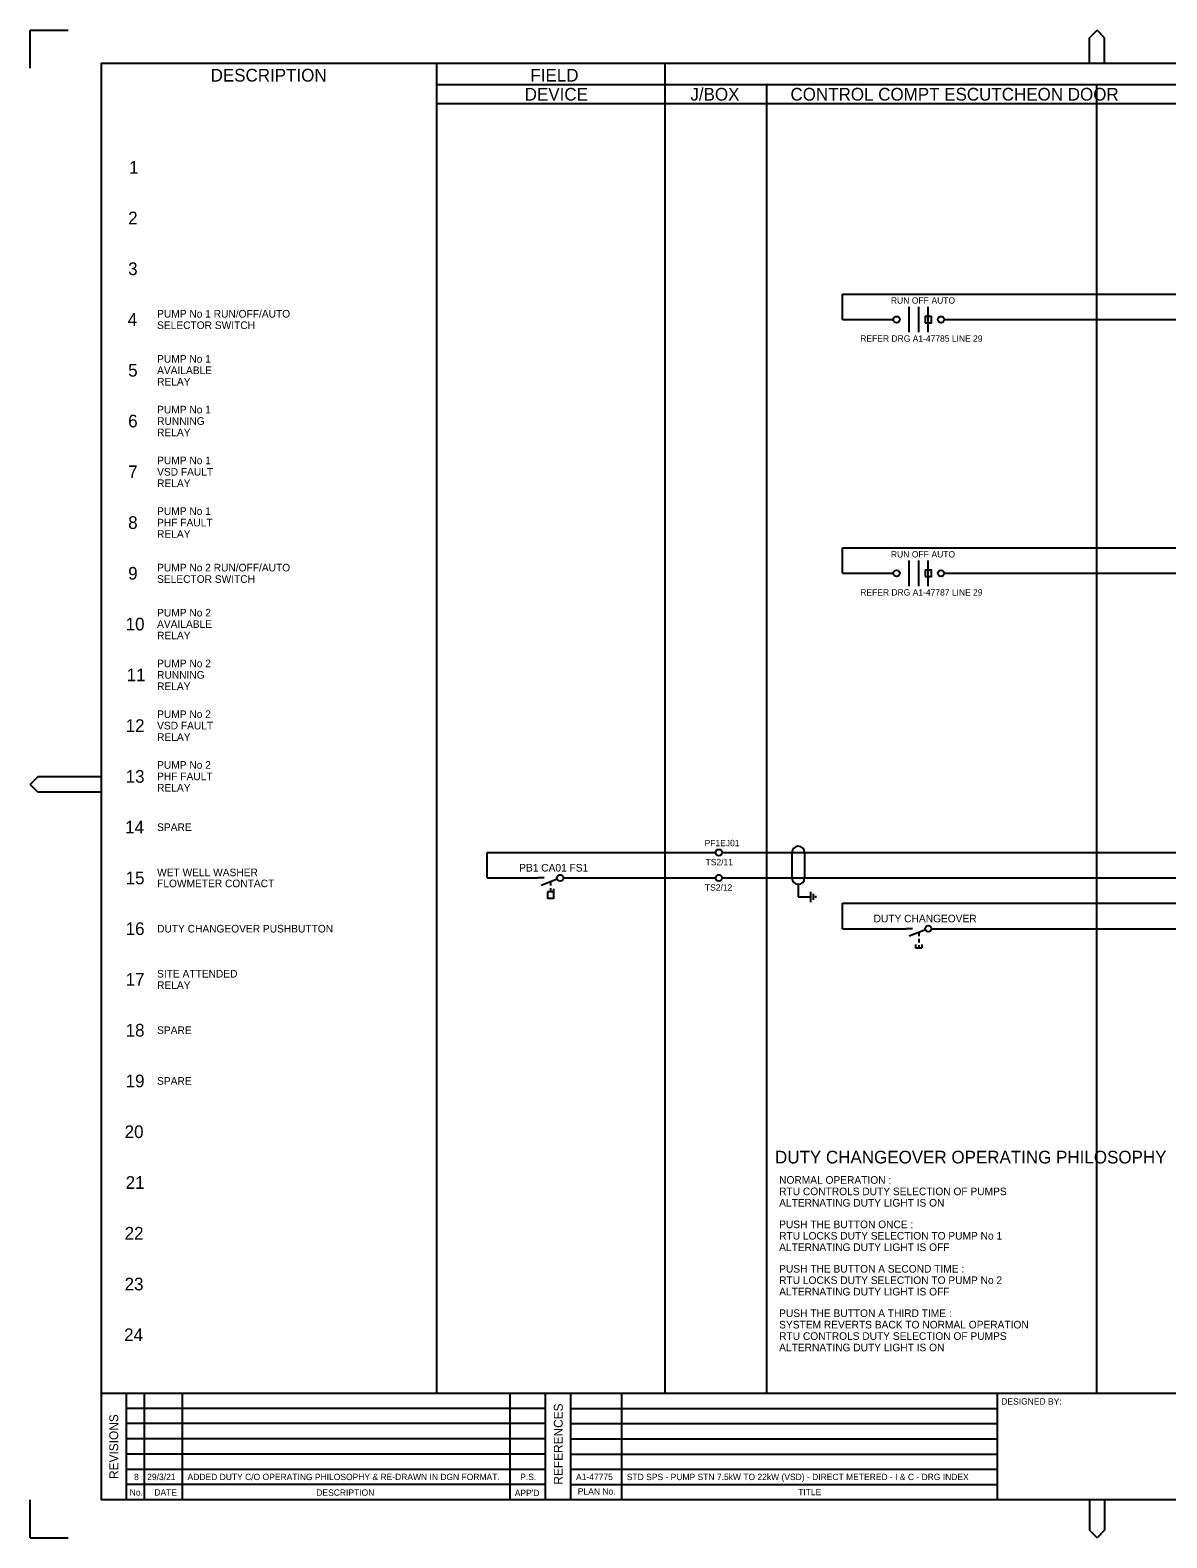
# Model space of a CAD drawing. Extents: x 0 to 841, y 0 to 594.
# Drawn here: x 0 to 448, y 0 to 594 of the extents above; entities that cross this region are included whole.
import ezdxf

# ---------------------------------------------------------------- set-up
doc = ezdxf.new("R2010")
doc.units = 0
for name, color, linetype in [('A1BORDER', 7, 'Continuous'), ('Level 1', 7, 'Continuous'), ('Level 10', 7, 'Continuous'), ('Level 5', 7, 'Continuous')]:
    doc.layers.add(name, color=color, linetype=linetype)

msp = doc.modelspace()

# ---------------------------------------------------------------- linework, layer by layer
at = {"layer": 'A1BORDER'}
for p, q in [((0, 594), (15, 594)), ((0, 579), (0, 594)), ((417.19, 591), (420.19, 594)), ((417.19, 581), (417.19, 591)), ((423.19, 591), (420.19, 594)), ((423.19, 581), (423.19, 591)), ((28, 581), (829, 581)), ((28, 581), (28, 15)), ((3, 299.76), (0, 296.76)), ((28, 299.76), (3, 299.76)), ((3, 293.76), (0, 296.76)), ((28, 293.76), (3, 293.76)), ((28, 57), (829, 57)), ((38, 15), (38, 57)), ((45, 15), (45, 57)), ((60, 15), (60, 57)), ((189, 15), (189, 57)), ((203, 15), (203, 57)), ((213, 15), (213, 57)), ((233, 15), (233, 57)), ((381, 15), (381, 57)), ((203, 51), (38, 51)), ((213, 51), (381, 51)), ((203, 45), (38, 45)), ((213, 45), (381, 45)), ((203, 39), (38, 39)), ((213, 39), (381, 39)), ((203, 33), (38, 33)), ((213, 33), (381, 33)), ((38, 27), (203, 27)), ((213, 27), (381, 27)), ((203, 21), (38, 21)), ((213, 21), (381, 21)), ((0, 0), (0, 15)), ((829, 15), (28, 15)), ((417.19, 15), (417.19, 3)), ((423.19, 15), (423.19, 3)), ((417.19, 3), (420.19, 0)), ((423.19, 3), (420.19, 0)), ((0, 0), (15, 0))]:
    msp.add_line(p, q, dxfattribs=at)
at = {"layer": 'Level 1'}
for p, q in [((160, 581), (160, 57)), ((250, 581), (250, 57)), ((829, 572.5), (160, 572.5)), ((290, 572.5), (290, 57)), ((420, 572.5), (420, 57)), ((829, 565), (160, 565)), ((320, 480), (320, 490)), ((320, 490), (520, 490)), ((346.25, 475), (346.25, 485)), ((350, 475), (350, 485)), ((353.75, 475), (353.75, 485)), ((320, 480), (340, 480)), ((360, 480), (520, 480)), ((320, 380), (320, 390)), ((320, 390), (520, 390)), ((346.25, 375), (346.25, 385)), ((350, 375), (350, 385)), ((353.75, 375), (353.75, 385)), ((320, 380), (340, 380)), ((360, 380), (520, 380)), ((180, 260), (180, 270)), ((180, 270), (270, 270)), ((270, 270), (270, 270)), ((272.5, 270), (272.5, 270)), ((272.5, 270), (608.75, 270)), ((300, 270), (300, 260)), ((305, 270), (305, 260)), ((180, 260), (200, 260)), ((202.5, 260), (200, 260)), ((200, 260), (200, 260)), ((210, 260), (210, 260)), ((210, 260), (270, 260)), ((270, 260), (270, 260)), ((272.5, 260), (272.5, 260)), ((272.5, 260), (690, 260)), ((302.5, 257.5), (302.5, 252.5)), ((302.5, 252.5), (307.5, 252.5)), ((320, 240), (320, 250)), ((320, 250), (608.75, 250)), ((320, 240), (345, 240)), ((347.5, 240), (345, 240)), ((345, 240), (345, 240)), ((355, 240), (355, 240)), ((355, 240), (690, 240))]:
    msp.add_line(p, q, dxfattribs=at)
for points in [[(352.5, 478.75), (355, 478.75), (355, 481.25), (352.5, 481.25)], [(352.5, 378.75), (355, 378.75), (355, 381.25), (352.5, 381.25)]]:
    msp.add_lwpolyline(points, close=True, dxfattribs=at)
for centre in [(341.25, 480), (358.75, 480), (341.25, 380), (358.75, 380)]:
    msp.add_circle(centre, 1.25, dxfattribs=at)
for centre, start, end in [((302.5, 270), 0, 180), ((302.5, 260), 180, 0)]:
    msp.add_arc(centre, 2.5, start, end, dxfattribs=at)
at = {"layer": 'Level 10'}
for p, q in [((207.59, 259.54), (201.25, 257)), ((205, 258.5), (205, 257)), ((205, 256), (205, 254.5)), ((206.25, 254.5), (206.25, 255.75)), ((307.5, 250.5), (307.5, 254.5)), ((308.5, 251.3), (308.5, 253.7)), ((309.5, 252.1), (309.5, 252.9)), ((352.59, 239.54), (346.25, 237)), ((350, 238.5), (350, 237)), ((348.75, 233.75), (348.75, 232.5)), ((348.75, 232.5), (351.25, 232.5)), ((350, 236), (350, 234.5)), ((350, 233.5), (350, 232.5)), ((351.25, 233.75), (351.25, 232.5))]:
    msp.add_line(p, q, dxfattribs=at)
msp.add_lwpolyline([(203.75, 254.5), (203.75, 252), (206.25, 252), (206.25, 254.5)], close=True, dxfattribs=at)
for centre in [(271.25, 270), (208.75, 260), (271.25, 260), (353.75, 240)]:
    msp.add_circle(centre, 1.25, dxfattribs=at)

# ---------------------------------------------------------------- texts
at = {"layer": 'A1BORDER'}
for s, p in [('DESIGNED BY:', (382.5, 52.5)), ('No.', (39.21, 16.65)), ('DATE', (48.92, 16.65)), ('DESCRIPTION', (112.71, 16.57)), ("APP'D", (190.85, 16.44)), ('PLAN No.', (215.69, 17.06)), ('TITLE', (302.5, 16.81))]:
    msp.add_text(s, height=2.5, dxfattribs=at).set_placement(p)
for s, p in [('REVISIONS', (34.68, 23.2)), ('REFERENCES', (209.76, 20.96))]:
    msp.add_text(s, height=3.5, rotation=90, dxfattribs=at).set_placement(p)
at = {"layer": 'Level 1'}
for s, height, p in [('DESCRIPTION', 5, (71.08, 573.75)), ('FIELD', 5, (197.03, 573.75)), ('DEVICE', 5, (194.79, 566.25)), ('J/BOX', 5, (260.04, 566.25)), ('CONTROL COMPT ESCUTCHEON DOOR', 5, (299.46, 566.25)), ('1', 5, (39, 537.5)), ('2', 5, (38.6, 517.5)), ('3', 5, (38.6, 497.5)), ('RUN', 2.5, (339.02, 486.25)), ('OFF', 2.5, (347.26, 486.25)), ('AUTO', 2.5, (355, 486.25)), ('4', 5, (38.4, 477.5)), ('PUMP No 1 RUN/OFF/AUTO', 3, (50, 480.75)), ('SELECTOR SWITCH', 3, (50, 476.25)), ('PUMP No 1', 3, (50, 463)), ('5', 5, (38.6, 457.5)), ('AVAILABLE', 3, (50, 458.5)), ('RELAY', 3, (50, 454)), ('PUMP No 1', 3, (50, 443)), ('6', 5, (38.6, 437.5)), ('RUNNING', 3, (50, 438.5)), ('RELAY', 3, (50, 434)), ('7', 5, (38.6, 417.5)), ('PUMP No 1', 3, (50, 423)), ('VSD FAULT', 3, (50, 418.5)), ('RELAY', 3, (50, 414)), ('PUMP No 1', 3, (50, 403)), ('8', 5, (38.6, 397.5)), ('PHF FAULT', 3, (50, 398.5)), ('RELAY', 3, (50, 394)), ('RUN', 2.5, (339.02, 386.25)), ('OFF', 2.5, (347.26, 386.25)), ('AUTO', 2.5, (355, 386.25)), ('9', 5, (38.6, 377.5)), ('PUMP No 2 RUN/OFF/AUTO', 3, (50, 380.75)), ('SELECTOR SWITCH', 3, (50, 376.25)), ('10', 5, (37.61, 357.5)), ('PUMP No 2', 3, (50, 363)), ('AVAILABLE', 3, (50, 358.5)), ('RELAY', 3, (50, 354)), ('PUMP No 2', 3, (50, 343)), ('11', 5, (38.01, 337.5)), ('RUNNING', 3, (50, 338.5)), ('RELAY', 3, (50, 334)), ('12', 5, (37.61, 317.5)), ('VSD FAULT', 3, (50, 318.5)), ('PUMP No 2', 3, (50, 323)), ('RELAY', 3, (50, 314)), ('PUMP No 2', 3, (50, 303)), ('13', 5, (37.61, 297.5)), ('PHF FAULT', 3, (50, 298.5)), ('RELAY', 3, (50, 294)), ('14', 5, (37.41, 277.5)), ('SPARE', 3, (50, 278.5)), ('PF1EJ01', 2.5, (265.65, 272.5)), ('TS2/11', 2.5, (266.02, 265)), ('15', 5, (37.61, 257.5)), ('WET WELL WASHER', 3, (50, 260.67)), ('FLOWMETER CONTACT', 3, (50, 256.33)), ('TS2/12', 2.5, (265.77, 255)), ('16', 5, (37.61, 237.5)), ('DUTY CHANGEOVER PUSHBUTTON', 3, (50, 238.5)), ('17', 5, (37.61, 217.5)), ('SITE ATTENDED', 3, (50, 220.75)), ('RELAY', 3, (50, 216.25)), ('18', 5, (37.61, 197.5)), ('SPARE', 3, (50, 198.5)), ('19', 5, (37.61, 177.5)), ('SPARE', 3, (50, 178.5)), ('20', 5, (37.21, 157.5)), ('DUTY CHANGEOVER OPERATING PHILOSOPHY', 5, (293.37, 147.5)), ('21', 5, (37.61, 137.5)), ('NORMAL OPERATION :', 3, (295, 139.5)), ('RTU CONTROLS DUTY SELECTION OF PUMPS', 3, (295, 135)), ('ALTERNATING DUTY LIGHT IS ON', 3, (295, 130.5)), ('PUSH THE BUTTON ONCE :', 3, (295, 122)), ('22', 5, (37.21, 117.5)), ('RTU LOCKS DUTY SELECTION TO PUMP No 1', 3, (295, 117.5)), ('ALTERNATING DUTY LIGHT IS OFF', 3, (295, 113)), ('PUSH THE BUTTON A SECOND TIME :', 3, (295, 104.5)), ('23', 5, (37.21, 97.5)), ('RTU LOCKS DUTY SELECTION TO PUMP No 2', 3, (295, 100)), ('ALTERNATING DUTY LIGHT IS OFF', 3, (295, 95.5)), ('PUSH THE BUTTON A THIRD TIME :', 3, (295, 87)), ('SYSTEM REVERTS BACK TO NORMAL OPERATION', 3, (295, 82.5)), ('24', 5, (37.01, 77.5)), ('RTU CONTROLS DUTY SELECTION OF PUMPS', 3, (295, 78)), ('ALTERNATING DUTY LIGHT IS ON', 3, (295, 73.5)), ('8', 2.5, (40.94, 22.75)), ('29/3/21', 2.5, (46.09, 22.75)), ('ADDED DUTY C/O OPERATING PHILOSOPHY & RE-DRAWN IN DGN FORMAT.', 2.5, (62, 22.75)), ('P.S.', 2.5, (193.02, 22.75)), ('A1-47775', 2.5, (215, 22.75)), ('STD SPS - PUMP STN 7.5kW TO 22kW (VSD) - DIRECT METERED - I & C - DRG INDEX', 2.5, (235, 22.75))]:
    msp.add_text(s, height=height, dxfattribs=at).set_placement(p)
at = {"layer": 'Level 5'}
for s, height, p in [('REFER DRG A1-47785 LINE 29', 2.5, (326.97, 471.25)), ('REFER DRG A1-47787 LINE 29', 2.5, (326.97, 371.25)), ('DUTY CHANGEOVER', 3, (332.22, 242.5))]:
    msp.add_text(s, height=height, dxfattribs=at).set_placement(p)
msp.add_text('PB1 CA01 FS1', height=3, rotation=360, dxfattribs=at).set_placement((192.6, 262.5))

doc.saveas('drawing.dxf')
